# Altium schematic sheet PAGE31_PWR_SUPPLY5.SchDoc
size 431 x 304 mm; SheetNumber: 28; SheetTotal: 28
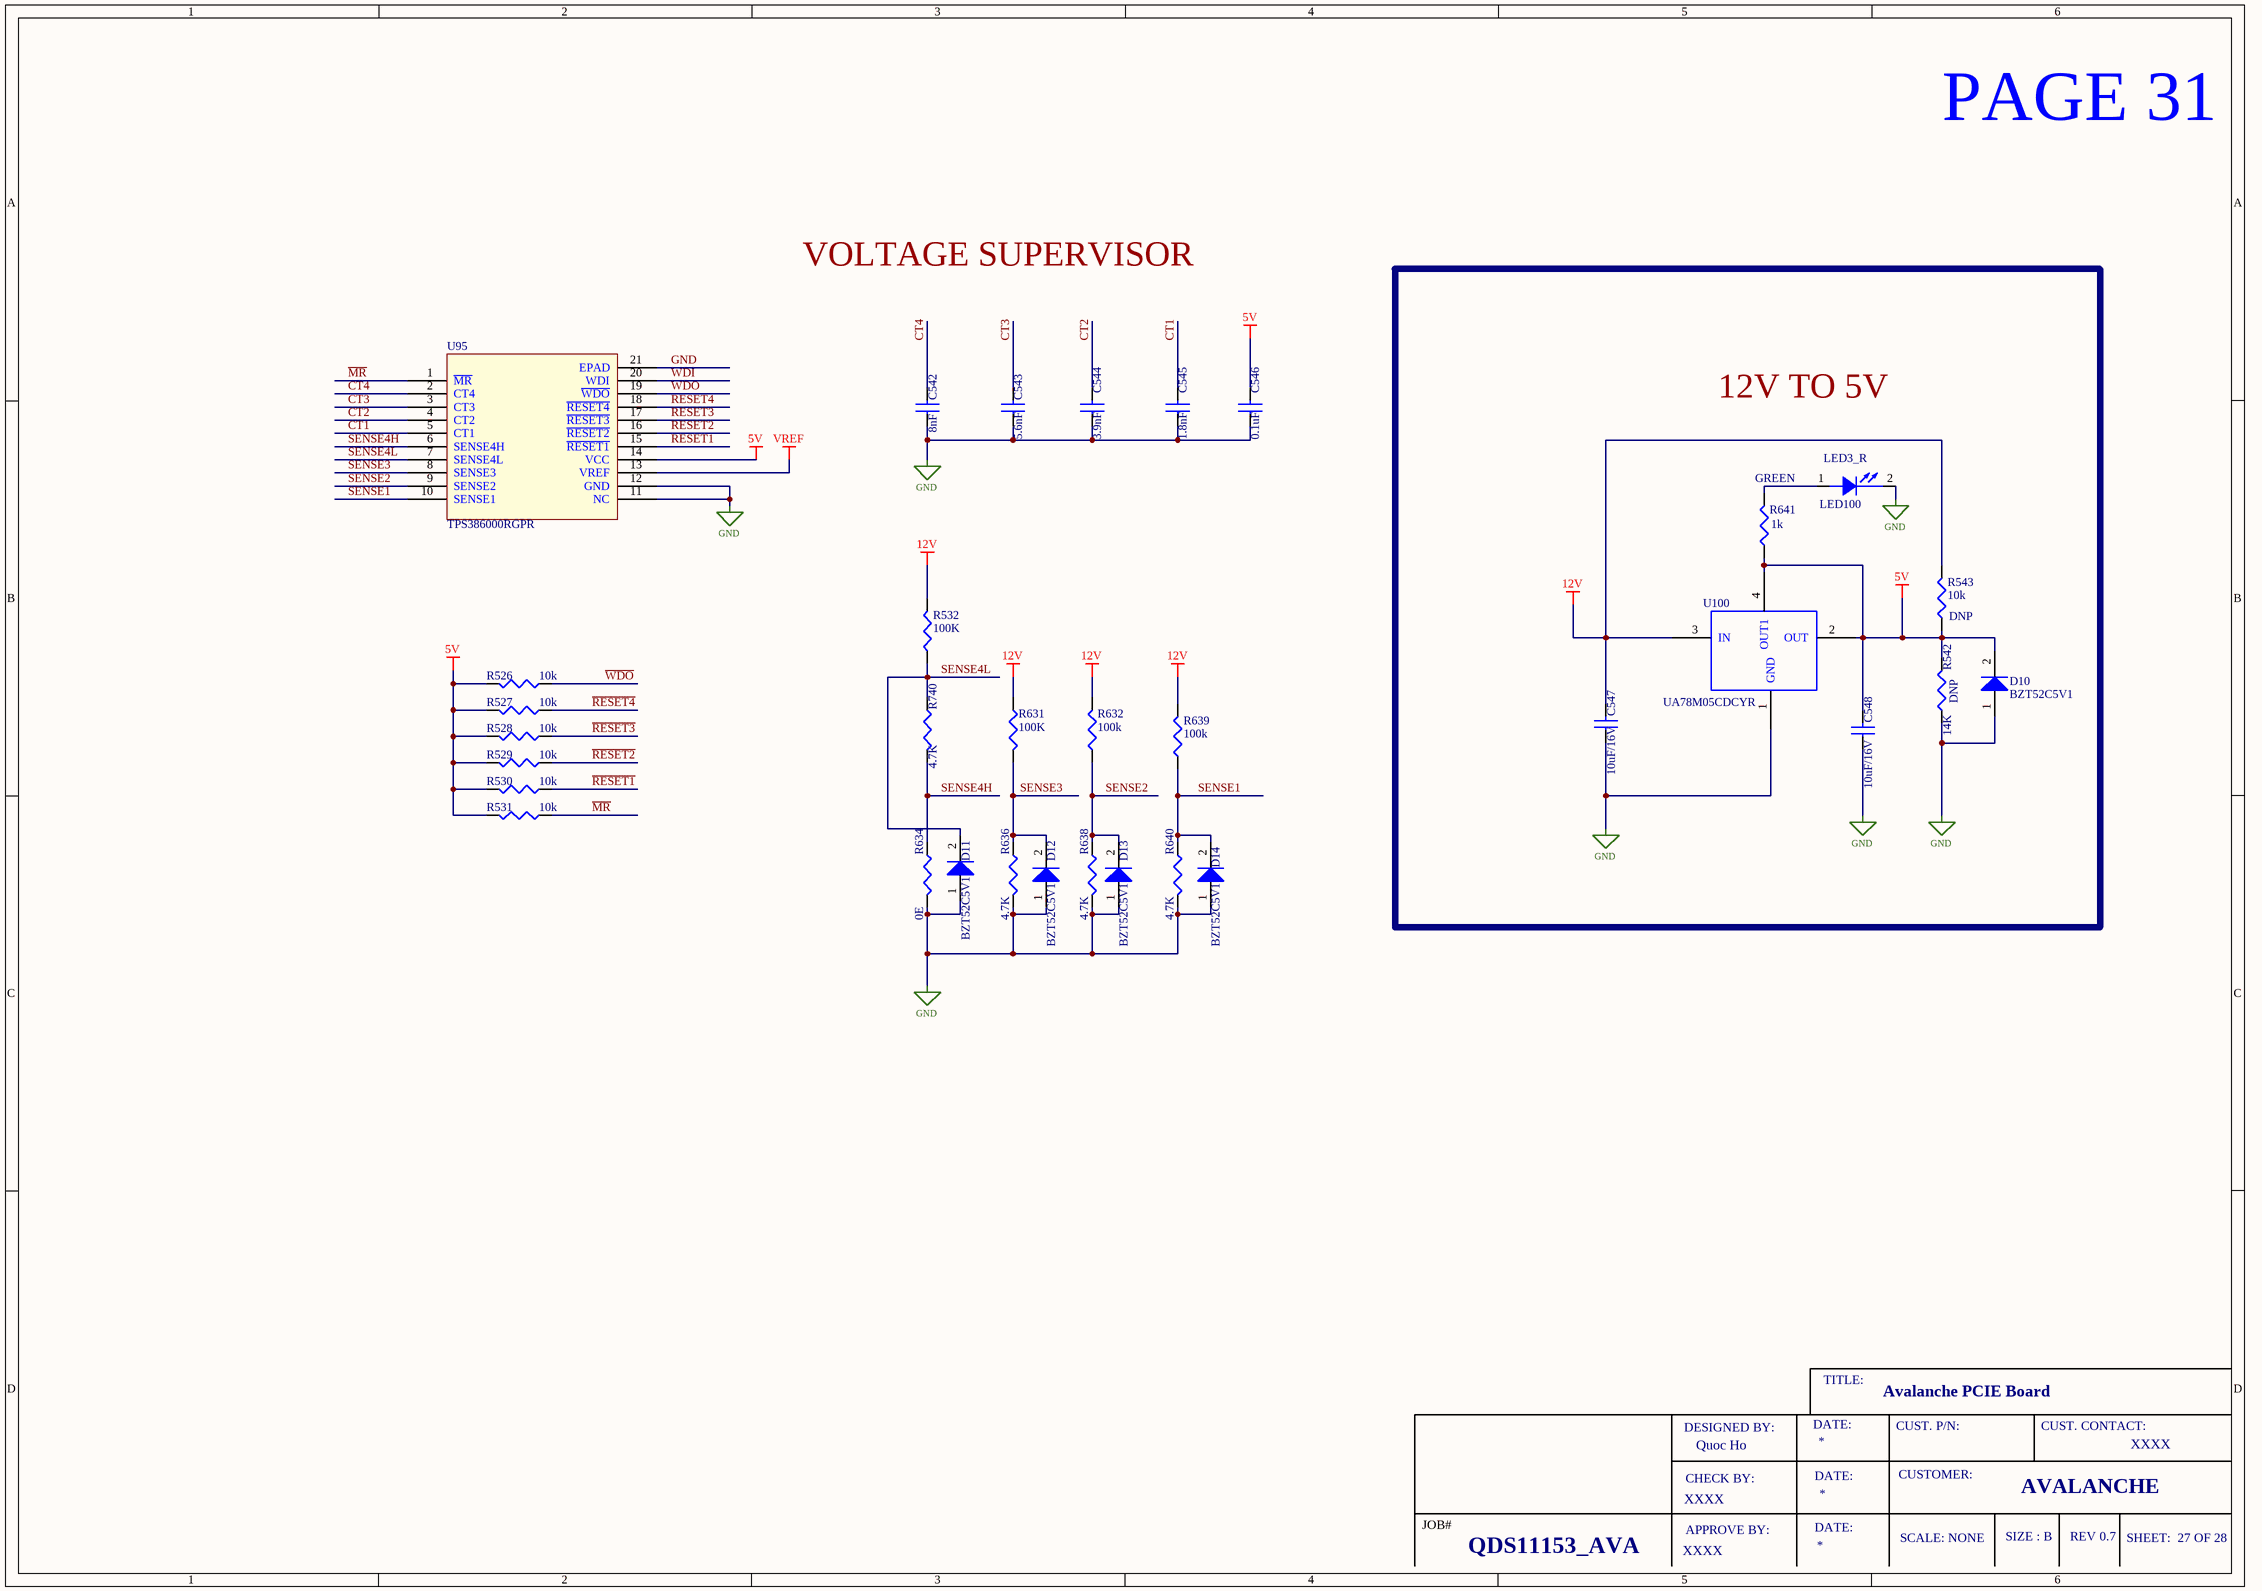
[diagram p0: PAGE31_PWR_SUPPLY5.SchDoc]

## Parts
C542  8nF  [CN_0402]
C543  5.6nF  [CN_0402]
C544  3.9nF  [CN_0402]
C545  1.8nF  [CN_0402]
C546  0.1uF  [CN_0402]
C547  10uF/16V  [CN_0805]
C548  10uF/16V  [CN_0805]
D10  BZT52C5V1  [BAS40 - SOD523]
D11  BZT52C5V1  [BAS40 - SOD523]
D12  BZT52C5V1  [BAS40 - SOD523]
D13  BZT52C5V1  [BAS40 - SOD523]
D14  BZT52C5V1  [BAS40 - SOD523]
LED100  GREEN  [LED_0603]
R526  10k  [RN_0402]
R527  10k  [RN_0402]
R528  10k  [RN_0402]
R529  10k  [RN_0402]
R530  10k  [RN_0402]
R531  10k  [RN_0402]
R532  100K  [RN_0402]
R542  14K  [RN_0402]
R543  10k  [RN_0402]
R631  100K  [RN_0402]
R632  100k  [RN_0402]
R634  0E  [RN_0402]
R636  4.7K  [RN_0402]
R638  4.7K  [RN_0402]
R639  100k  [RN_0402]
R640  4.7K  [RN_0402]
R641  1k  [RN_0402]
R740  4.7K  [RN_0402]
U95  TPS386000RGPR  [QFN20_RGB_4P15X4P15X1_TEX]
U100  UA78M05CDCYR  [VREG_SOT223-4_6P5X3P5X1P8]

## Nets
5V: C546.2 C548.2 D10.2(K) R526.2 R527.2 R528.2 R529.2 R530.2 R531.2 R542.2 R543.1 R641.1 U95.14(VCC) U100.2(OUT) U100.4(OUT1)
12V: C547.2 R532.2 R543.2 R631.1 R632.2 R639.2 U100.3(IN)
GND: C542.1 C543.1 C544.1 C545.1 C546.1 C547.1 C548.1 D10.1(A) D11.1(A) D12.1(A) D13.1(A) D14.1(A) LED100.2 R542.1 R634.2 R636.2 R638.2 R640.2 U95.11(NC) U95.12(GND) U95.21(EPAD) U100.1(GND)
VREF: U95.13(VREF)
CT1: C545.2 U95.5(CT1)
CT2: C544.2 U95.4(CT2)
CT3: C543.2 U95.3(CT3)
CT4: C542.2 U95.2(CT4)
~{MR}: R531.1 U95.1(~{MR})
~{RESET1}: R530.1 U95.15(~{RESET1})
~{RESET2}: R529.1 U95.16(~{RESET2})
~{RESET3}: R528.1 U95.17(~{RESET3})
~{RESET4}: R527.1 U95.18(~{RESET4})
SENSE1: D14.2(K) R639.1 R640.1 U95.10(SENSE1)
SENSE2: D13.2(K) R632.1 R638.1 U95.9(SENSE2)
SENSE3: D12.2(K) R631.2 R636.1 U95.8(SENSE3)
SENSE4H: R634.1 R740.2 U95.6(SENSE4H)
SENSE4L: D11.2(K) R532.1 R740.1 U95.7(SENSE4L)
~{WDO}: R526.1 U95.19(~{WDO})
WDI: U95.20(WDI)
NetLED100_1: LED100.1 R641.2

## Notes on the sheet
- PAGE 31
- VOLTAGE SUPERVISOR
- 12V TO 5V
- (near LED100) LED3_R
- (near R543) DNP
- (near R542) DNP
- TITLE:
- Avalanche PCIE Board
- DESIGNED BY:
- CHECK BY:
- Quoc Ho
- DATE:
- CUST. P/N:
- CUSTOMER:
- CUST. CONTACT:
- XXXX
- JOB#
- APPROVE BY:
- SCALE: NONE
- SIZE : B
- AVALANCHE
- REV 0.7
- SHEET:  27 OF 28
- QDS11153_AVA

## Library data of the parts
C542 = CAP: CAP CER 8200PF 25V X7R 0402; Manufacturer: KEMET; Manufacturer Part Number: C0402C822J3RACTU
C543 = CAP: CAP CER 5600PF 50V X7R 0402; Manufacturer: KEMET; Manufacturer Part Number: C0402C562K5RACTU
C544 = CAP: CAP CER 3900PF 50V X7R 0402; Manufacturer: KYOCERA AVX; Manufacturer Part Number: KGM05AR71H392JH
C545 = CAP: CAP CER 1800PF 50V U2J 0402; Manufacturer: KEMET; Manufacturer Part Number: C0402C182J5JACTU
C546 = CAP: CAP CER 0.1UF 50V X7R 0402; Manufacturer: Murata Electronics; Manufacturer Part Number: GCM155R71H104KE02J
C547 C548 = CAP_POLAR: 10 µF ±10% 16V Ceramic Capacitor X5R 0805 (2012 Metric); Manufacturer: Samsung Electro-Mechanics; Manufacturer Part Number: CL21A106KOQNNNE
D10-D14 = BZT52C5V1: DIODE ZENER 5.1V 200MW SOD523; Manufacturer: Micro Commercial Co; Manufacturer Part Number: BZT52C5V1T-TP; Reverse Recovery Time-Max: 1ns; Power Dissipation: 500mW
LED100 = LED: LED GREEN CLEAR SMD; Manufacturer Part Number: LTST-C191KGKT; Manufacturer: Lite-On Inc.
R526-R531 R543 = RES: RES 10K OHM 1% 1/16W 0402; Manufacturer Part Number: RC0402FR-0710KL; Manufacturer: YAGEO
R532 R631 R632 R639 = RES: RES 100K OHM 1% 1/16W 0402; Manufacturer Part Number: RC0402FR-07100KL; Manufacturer: YAGEO
R542 = RES: RES 14K OHM 1% 1/16W 0402; Manufacturer Part Number: RC0402FR-0714KL; Manufacturer: YAGEO
R634 = RES: RES 0 OHM JUMPER 1/16W 0402; Manufacturer Part Number: RC0402FR-070RL; Manufacturer: YAGEO
R636 R638 R640 R740 = RES: RES 4.7K OHM 1% 1/16W 0402; Manufacturer Part Number: RC0402FR-134K7L; Manufacturer: YAGEO
R641 = RES: RES 1K OHM 1% 1/16W 0402; Manufacturer Part Number: RC0402FR-131KL; Manufacturer: YAGEO
U95 = TPS386000RGPR: IC SUPERVISOR 4 CHANNEL 20QF; Manufacturer: Texas Instruments
U100 = REG: IC REG LINEAR 5V 500MA SOT223-4; Manufacturer: Texas Instruments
